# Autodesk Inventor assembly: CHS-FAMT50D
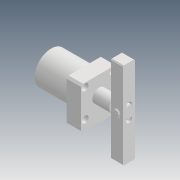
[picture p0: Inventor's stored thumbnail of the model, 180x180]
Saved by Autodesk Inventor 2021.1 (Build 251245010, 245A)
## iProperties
Created: 2019-04
Part Number: CHS-FAMT50D
Description: STEP AP203
Document SubType Name: Assembly
Designer: user
Title: chs-famt50d_asm.STEP
Revision Number: ÈÎºÎ
Sending System: SolidWorks 2017
Preprocessor: SwSTEP 2.0
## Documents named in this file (10)
- D:\Vault_2016\Projekty\Clamptek\Hydraulic\CHS\CHS-50\Inventor\CHS-FAMT50D\CHS-FAMT50D.iam
- D:\Vault_2016\Projekty\Clamptek\Hydraulic\CHS\CHS-50\Inventor\CHS-FAMT50D\CHS-FAMT50  BT_1.ipt
- D:\Vault_2016\Projekty\Clamptek\Hydraulic\CHS\CHS-50\Inventor\CHS-FAMT50D\M4_1.ipt
- D:\Vault_2016\Projekty\Clamptek\Hydraulic\CHS\CHS-50\Inventor\CHS-FAMT50D\CHS-50DHSG_5.ipt
- D:\Vault_2016\Projekty\Clamptek\Hydraulic\CHS\CHS-50\Inventor\CHS-FAMT50D\CHS-50DYB_7.ipt
- D:\Vault_2016\Projekty\Clamptek\Hydraulic\CHS\CHS-50\Inventor\CHS-FAMT50D\ÖáÓÃµ²È¦.ipt
- D:\Vault_2016\Projekty\Clamptek\Hydraulic\CHS\CHS-50\Inventor\CHS-FAMT50D\Ïú.ipt
- D:\Vault_2016\Projekty\Clamptek\Hydraulic\CHS\CHS-50\Inventor\CHS-FAMT50D\20·§Ìå.ipt
- D:\Vault_2016\Projekty\Clamptek\Hydraulic\CHS\CHS-50\Inventor\CHS-FAMT50D\20µ÷ËÙ¸Ë.ipt
- D:\Vault_2016\Projekty\Clamptek\Hydraulic\CHS\CHS-50\Inventor\CHS-FAMT50D\hex thin nuts-grades ab-chamfered gb(GB_FASTENER_NUT_STNAB M6-S).ipt
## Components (12 placed, 12 different names)
1. CHS-FAMT50  BT_1_1
2. M4_1_2
3. M4_1_3
4. M4_1_4
5. CHS-50DHSG_5_5
6. CHS-50DYB_7_6
7. ÖáÓÃµ²È¦_7
8. Ïú_8
9. 20·§Ìå_9
10. 20µ÷ËÙ¸Ë_10
11. hex thin nuts-grades ab-chamfered gb(GB_FASTENER_NUT_STNAB M6-S)_11
12. ÖáÓÃµ²È¦_12
